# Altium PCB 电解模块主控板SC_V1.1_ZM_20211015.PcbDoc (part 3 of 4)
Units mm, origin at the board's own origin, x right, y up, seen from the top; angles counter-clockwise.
Board outline 150.25 x 100.26 mm, 2 copper layers (Top Layer, Bottom Layer); 222 components, 167 nets, 677 pads, 2045 vias.
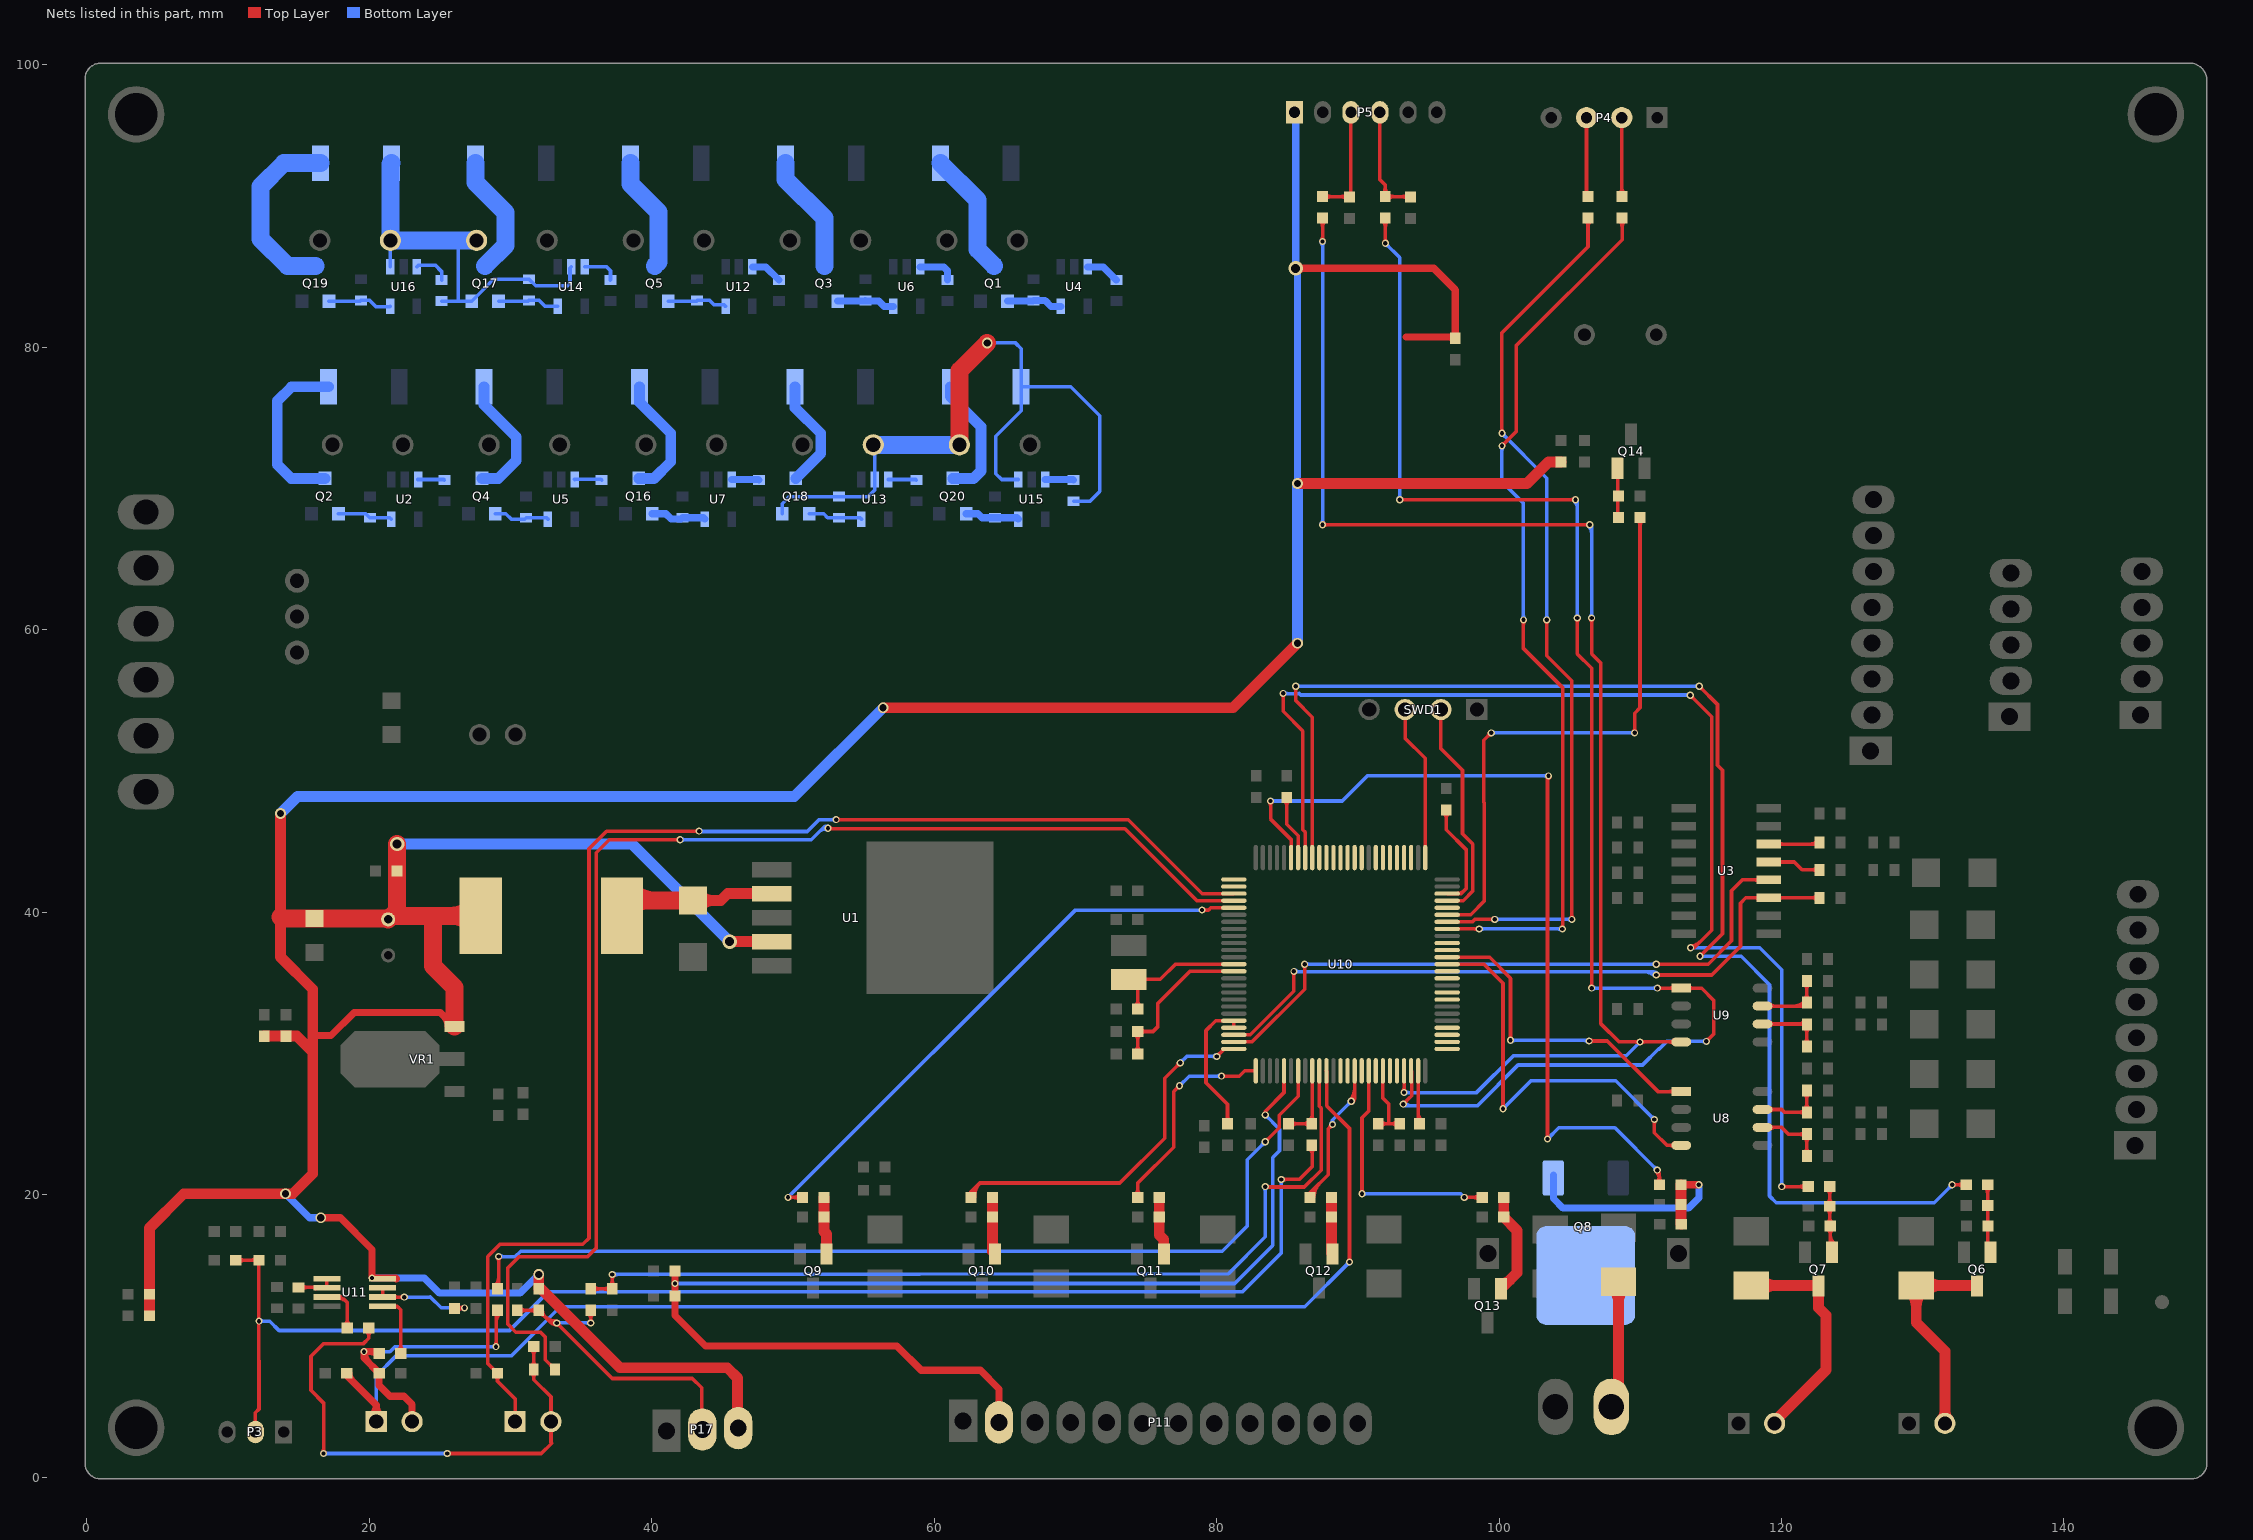
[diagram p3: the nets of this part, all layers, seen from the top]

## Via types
v1: diameter 0.762, hole 0.508, Top Layer to Bottom Layer, tented both sides, 1838 vias
v2: diameter 0.508, hole 0.305, Top Layer to Bottom Layer, tented both sides, 135 vias
v3: diameter 1.016, hole 0.635, Top Layer to Bottom Layer, tented both sides, 63 vias
v4: diameter 2.032, hole 1.524, Top Layer to Bottom Layer, tented both sides, 4 vias
v5: diameter 1.27, hole 0.762, Top Layer to Bottom Layer, tented both sides, 4 vias
v6: diameter 2.54, hole 2.032, Top Layer to Bottom Layer, tented both sides, 1 vias

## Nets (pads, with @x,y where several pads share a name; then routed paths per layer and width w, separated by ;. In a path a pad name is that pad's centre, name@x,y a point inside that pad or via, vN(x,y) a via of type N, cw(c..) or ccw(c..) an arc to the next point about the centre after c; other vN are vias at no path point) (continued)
NetC37_2: C37.2 R7.2 U10.44 | length 7.4
  Top Layer w0.254: R7.2@91.44,25.019 92.202,25.019 ; R7.2@91.62,24.839 cw(c92.053,24.406) 92.053,25.019 cw(c92.053,25.632) R7.2@91.62,25.199 ; U10.44@91.773,28.772 91.773,26.845 92.202,26.416 92.202,25.019 ; C37.2@92.784,24.839 ccw(c92.351,24.406) 92.351,25.019 ccw(c92.351,25.632) C37.2@92.784,25.199 ; C37.2@92.964,25.019 92.202,25.019
NetC38_2: C38.2 R8.2 U10.34 | length 8.3
  Top Layer w0.254: C38.2@85.09,25.019 R8.2@86.741,25.019 86.773,25.051 U10.34@86.773,28.772 ; C38.2@85.27,24.839 cw(c85.703,24.406) 85.703,25.019 cw(c85.703,25.632) C38.2@85.27,25.199 ; R8.2@86.561,24.839 ccw(c86.128,24.406) 86.128,25.019 ccw(c86.128,25.632) R8.2@86.561,25.199 ; R8.2@86.561,25.218 ccw(c86.051,25.728) 86.773,25.728 ; 86.773,25.574 ccw(c87.277,25.574) R8.2@86.921,25.218
NetC39_2: C39.2 U10.49 | length 4.8
  Top Layer w0.254: C39.2@94.181,25.218 ccw(c93.96,25.439) 94.273,25.439 ; 94.273,25.864 ccw(c95.187,25.864) C39.2@94.541,25.218 ; U10.49@94.273,28.772 94.273,25.107 C39.2@94.361,25.019
NetC40_2: C40.2 R78.1 U10.14 | length 14
  Top Layer w0.254: R78.1@74.242,30.152 ccw(c73.809,30.585) 74.422,30.585 ccw(c75.035,30.585) R78.1@74.602,30.152 ; C40.2@74.242,31.38 cw(c73.809,30.946) 74.422,30.946 cw(c75.035,30.946) C40.2@74.602,31.38 ; R78.1@74.422,29.972 C40.2@74.422,31.559 75.501,31.559 75.819,31.877 75.819,33.528 78.113,35.822 U10.14@81.223,35.822 ; C40.2@74.621,31.38 cw(c75.054,30.946) 75.054,31.559 cw(c75.054,32.173) C40.2@74.621,31.739
NetC41_2: C41.2 C43.1 Q17.2 R101.2 R103.1 R112.1 U14.2 U16.1 | length 29
  Bottom Layer w0.254: U16.1@21.478,85.7 21.478,87.558 C43.1@21.499,87.579 ; R112.1@25.121,83.272 26.314,83.272 ; 26.365,87.579 26.314,87.528 26.314,83.272 ; U14.2@34.303,85.7 34.214,85.611 34.214,84.506 34.061,84.353 31.781,84.353 R101.2@31.312,84.822 28.803,84.822 Q17.2@27.255,83.275 27.252,83.272 26.314,83.272
  Bottom Layer w1.27: R103.1@21.561,93.04 21.499,92.979 C43.1@21.499,87.579 26.365,87.579 C41.2@27.599,87.579
NetC42_2: C42.2 C44.1 Q18.2 R102.2 R107.1 R111.1 U13.2 U15.1 | length 52.9
  Top Layer w1.27: C44.1@61.787,73.101 61.787,78.348 v1(63.754,80.315)
  Bottom Layer w0.254: Q18.2@49.253,68.219 49.253,68.938 49.752,69.437 R102.2@53.245,69.437 55.34,69.437 55.804,69.901 U13.2@55.804,70.644 55.804,72.985 C42.2@55.688,73.101 ; v1(63.754,80.315) 65.761,80.315 66.163,79.912 R107.1@66.163,77.216 ; U15.1@65.954,70.644 64.78,70.644 64.364,71.061 64.364,73.711 66.163,75.51 R107.1@66.163,77.216 ; R111.1@69.875,69.105 71.035,69.105 71.73,69.799 71.73,75.159 69.672,77.216 R107.1@66.163,77.216
  Bottom Layer w1.27: C42.2@55.688,73.101 C44.1@61.787,73.101
NetC45_2: C45.2 U10.73 | length 9.1
  Top Layer w0.254: C45.2@96.086,47.045 cw(c95.653,46.612) 96.266,46.612 cw(c96.879,46.612) C45.2@96.446,47.045 ; C45.2@96.266,47.244 96.266,45.847 97.663,44.45 97.663,41.656 97.329,41.322 U10.73@96.323,41.322 ; U10.73@97.073,41.345 ccw(c97.073,42.019) 97.549,41.542
NetC46_2: C46.2 P11.2 R48.1 U10.30 | length 88.5
  Top Layer w0.254: v2(83.439,25.654) 83.439,25.899 84.773,27.233 U10.30@84.773,28.772
  Top Layer w0.508: R48.1@41.656,14.605 v2(41.656,13.716) C46.2@41.656,12.827 41.656,11.455 43.815,9.296 57.353,9.296 59.08,7.569 63.271,7.569 64.592,6.248 P11.2@64.592,3.888
  Bottom Layer w0.254: v2(41.656,13.716) 81.28,13.716 83.972,16.408 83.972,22.631 84.455,23.114 84.455,24.638 v2(83.439,25.654) ; v2@41.746,13.626 cw(c41.963,13.409) 41.963,13.716 cw(c41.963,14.023) v2@41.746,13.806 ; v2@83.439,25.527 cw(c83.439,25.22) 83.656,25.437 cw(c83.873,25.654) v2@83.566,25.654
NetC50_1: C50.1 U10.13 Y1.1 | length 11.2
  Top Layer w0.254: C50.1@74.242,33.327 ccw(c73.809,33.76) 74.422,33.76 ccw(c75.035,33.76) C50.1@74.602,33.327 ; C50.1@74.422,33.147 74.422,34.614 Y1.1@73.787,35.249 76.016,35.249 77.089,36.322 U10.13@81.223,36.322
NetD3_2: D3.2 L1.1 U1.2 | length 16.9
  Top Layer w0.762: L1.1@37.893,39.751 L1.1@38.972,40.83 ; D3.2@42.926,40.83 44.894,40.83 45.388,41.324 U1.2@48.514,41.324 ; D3.2@43.364,40.392 cw(c44.42,39.336) 44.42,40.83 cw(c44.42,42.324) D3.2@43.364,41.268
  Top Layer w1.27: L1.1@38.505,40.339 cw(c39.689,39.155) 39.689,40.83 ; L1.1@38.505,41.563 ccw(c40.273,43.331) 40.273,40.83 ; L1.1@38.972,40.83 D3.2@42.926,40.83
NetD6_1: D6.1 P8.2 Q6.3 | length 21
  Top Layer w0.762: D6.1@129.102,13.141 cw(c128.046,12.085) 129.54,12.085 cw(c131.034,12.085) D6.1@129.978,13.141 ; D6.1@130.228,13.141 cw(c131.284,12.085) 131.284,13.579 cw(c131.284,15.073) D6.1@130.228,14.017 ; P8.2@131.311,4.071 ccw(c130.681,4.701) 131.572,4.701 ccw(c132.463,4.701) P8.2@131.833,4.071 ; P8.2@131.572,3.81 131.572,8.915 129.54,10.947 D6.1@129.54,13.579 133.811,13.579 Q6.3@133.858,13.532
NetD7_1: D7.1 P9.2 Q7.3 | length 18.6
  Top Layer w0.762: D7.1@117.856,13.579 122.571,13.579 Q7.3@122.618,13.532 122.618,12.002 123.158,11.462 123.158,7.588 119.507,3.937 P9.2@119.507,3.81 ; D7.1@118.544,13.141 cw(c119.6,12.085) 119.6,13.579 cw(c119.6,15.073) D7.1@118.544,14.017
NetD8_1: D8.1 P10.2 Q8.3 | length 13
  Top Layer w0.762: P10.2@107.315,3.937 107.315,5.182 108.458,6.325 D8.1@108.458,13.833 D8.1@108.632,13.659 ; D8.1@108.02,13.395 cw(c106.964,12.339) 108.458,12.339 cw(c109.952,12.339) D8.1@108.896,13.395
NetL3_2: L3.2 U10.21 U10.22 | length 11
  Top Layer w0.254: L3.2@80.592,25.218 ccw(c80.159,25.651) 80.772,25.651 ccw(c81.385,25.651) L3.2@80.952,25.218 ; L3.2@80.772,25.019 80.772,26.416 79.248,27.94 79.248,31.623 79.947,32.322 U10.21@81.223,32.322 U10.22@81.223,31.822
NetP1_1: P1.1 TVS5.2 U10.36 | length 97.4
  Top Layer w0.254: U10.36@87.773,28.772 87.808,28.737 87.808,26.289 89.408,24.689 v2(89.408,15.24) ; v2@89.318,15.33 ccw(c89.101,15.547) 89.408,15.547 ccw(c89.715,15.547) v2@89.498,15.33
  Top Layer w0.508: TVS5.2@18.415,7.366 18.415,7.188 20.498,5.105 ; TVS5.2@18.561,7.366 ccw(c19.343,7.366) 18.79,6.813 ; P1.1@20.153,4.294 ccw(c19.37,5.105) 20.498,5.105 ; P1.1@20.498,3.937 20.498,5.105 ; P1.1@20.842,4.294 cw(c21.626,5.105) 20.498,5.105
  Bottom Layer w0.254: P1.1@20.498,3.937 20.498,7.188 21.895,8.585 30.048,8.585 33.528,12.065 86.233,12.065 v2(89.408,15.24) ; v2@89.281,15.24 cw(c88.974,15.24) 89.191,15.023 cw(c89.408,14.806) v2@89.408,15.113
NetP1_2: P1.2 R14.2 R16.1 TVS6.2 | length 24
  Top Layer w0.254: v2@28.892,9.335 ccw(c28.675,9.552) 28.981,9.552 ccw(c29.288,9.552) v2@29.071,9.335 ; R14.2@28.903,11.612 cw(c28.715,11.424) R14.2@28.981,11.424 ; v2(28.981,9.246) 28.981,11.709 R14.2@29.083,11.811 ; 28.981,10.934 cw(c29.941,10.934) R14.2@29.263,11.612
  Top Layer w0.508: 19.957,8.11 cw(c20.738,8.89) v2(19.634,8.89) ; 20.069,8.89 cw(c20.069,8.15) R16.1@20.592,8.673 ; R16.1@20.701,8.763 20.574,8.89 v2(19.634,8.89) ; P1.2@23.038,3.937 23.038,5.156 22.466,5.728 21.467,5.728 20.701,6.494 TVS6.2@20.701,7.366 19.634,8.433 v2(19.634,8.89)
  Bottom Layer w0.254: v2(19.634,8.89) 21.463,8.89 21.819,9.246 v2(28.981,9.246) ; v2@19.724,8.8 cw(c19.941,8.583) 19.941,8.89 cw(c19.941,9.197) v2@19.724,8.98 ; v2@28.892,9.156 ccw(c28.675,8.939) 28.675,9.246 ccw(c28.675,9.552) v2@28.892,9.335
NetP2_1: P2.1 TVS7.2 U10.3 | length 99.1
  Top Layer w0.254: TVS7.2@28.91,7.18 cw(c28.538,6.782) 29.083,6.782 ; TVS7.2@29.256,7.18 ccw(c29.628,6.782) 29.083,6.782 ; P2.1@30.328,3.937 30.328,5.537 29.083,6.782 ; v2@43.268,45.656 ccw(c43.051,45.439) 43.051,45.745 ccw(c43.051,46.052) v2@43.268,45.835 ; v2(43.358,45.745) 36.805,45.745 35.56,44.501 35.56,16.916 35.128,16.485 29.261,16.485 28.397,15.621 28.397,8.052 TVS7.2@29.083,7.366 29.083,6.782 ; v2(53.061,46.558) 73.736,46.558 78.972,41.322 U10.3@81.223,41.322 ; v2@53.15,46.468 cw(c53.367,46.252) 53.367,46.558 cw(c53.367,46.865) v2@53.15,46.648
  Bottom Layer w0.254: v2(43.358,45.745) 43.383,45.72 51.003,45.72 51.841,46.558 v2(53.061,46.558) ; v2@43.448,45.835 ccw(c43.726,46.113) 43.726,45.72 ; v2@52.971,46.468 ccw(c52.754,46.252) 52.754,46.558 ccw(c52.754,46.865) v2@52.971,46.648
NetP2_2: P2.2 R23.2 R25.1 TVS12.2 | length 42
  Top Layer w0.254: v2@16.674,1.766 ccw(c16.457,1.983) 16.764,1.983 ccw(c17.071,1.983) v2@16.854,1.766 ; v2(16.764,1.676) 16.764,5.258 15.875,6.147 15.875,8.56 16.777,9.461 19.596,9.461 19.964,9.83 R25.1@19.964,10.566 ; R25.1@19.785,10.387 cw(c19.351,9.953) 19.964,9.953 cw(c20.578,9.953) R25.1@20.144,10.387 ; v2(25.527,1.676) 32.182,1.676 32.918,2.413 32.868,2.464 P2.2@32.868,3.937 32.868,5.688 31.647,6.909 R23.2@31.647,7.62 ; v2@25.617,1.587 cw(c25.834,1.37) 25.834,1.676 cw(c25.834,1.983) v2@25.617,1.766 ; TVS12.2@31.469,9.066 cw(c31.035,8.632) 31.648,8.632 cw(c32.262,8.632) TVS12.2@31.828,9.066 ; R23.2@31.489,7.387 cw(c31.109,7.007) 31.647,7.007 cw(c32.185,7.007) R23.2@31.805,7.387 ; R23.2@31.489,7.853 ccw(c31.105,8.237) 31.648,8.237 ; R23.2@31.648,7.62 TVS12.2@31.648,9.246 ; 31.648,8.23 ccw(c32.182,8.23) R23.2@31.805,7.853
  Bottom Layer w0.254: v2(16.764,1.676) v2(25.527,1.676) ; v2@16.854,1.587 cw(c17.071,1.37) 17.071,1.676 cw(c17.071,1.983) v2@16.854,1.766 ; v2@25.437,1.587 ccw(c25.22,1.37) 25.22,1.676 ccw(c25.22,1.983) v2@25.437,1.766
NetP3_2: P3.2 R6.2 R8.1 TVS2.2 | length 102
  Top Layer w0.254: TVS2.2@10.541,15.367 R6.2@12.192,15.367 12.167,15.342 12.167,8.284 12.192,8.259 12.192,4.826 11.938,4.572 P3.2@11.938,3.2 ; TVS2.2@10.74,15.187 cw(c11.173,14.754) 11.173,15.367 cw(c11.173,15.98) TVS2.2@10.74,15.547 ; 11.56,15.367 ccw(c11.56,15.98) R6.2@11.993,15.547 ; v2(84.582,21.082) 85.852,21.082 86.766,21.996 86.766,23.47 R8.1@86.741,23.495 ; v2@84.672,20.992 cw(c84.889,20.775) 84.889,21.082 cw(c84.889,21.389) v2@84.672,21.172 ; R8.1@86.561,23.296 cw(c86.066,22.801) 86.766,22.801 ; 86.766,22.924 cw(c87.293,22.924) R8.1@86.921,23.296
  Bottom Layer w0.254: v2(12.192,11.049) 12.954,11.049 13.614,10.389 29.934,10.389 32.69,13.144 81.852,13.144 84.582,15.875 v2(84.582,21.082) ; v2@12.282,10.959 cw(c12.499,10.742) 12.499,11.049 cw(c12.499,11.356) v2@12.282,11.139 ; v2@84.492,20.992 cw(c84.275,20.775) 84.582,20.775 cw(c84.889,20.775) v2@84.672,20.992
NetP4_2: P4.2 R11.1 | length 6.6
  Top Layer w0.254: R11.1@108.532,90.877 ccw(c108.147,91.262) 108.692,91.262 ; 108.692,91.358 ccw(c109.373,91.358) R11.1@108.892,90.877 ; P4.2@108.692,96.266 108.692,90.698 R11.1@108.712,90.678
NetP4_3: P4.3 R9.1 | length 5.6
  Top Layer w0.254: P4.3@106.192,96.266 106.192,90.785 R9.1@106.299,90.678
NetP5_3: P5.3 R10.1 TVS3.2 | length 9.9
  Top Layer w0.254: R10.1@87.503,90.678 89.383,90.678 TVS3.2@89.408,90.653 89.511,90.755 P5.3@89.511,96.641 ; R10.1@87.683,90.498 cw(c88.116,90.065) 88.116,90.678 cw(c88.116,91.291) R10.1@87.683,90.858 ; 88.779,90.678 cw(c88.779,90.043) TVS3.2@89.228,90.492 ; 88.81,90.678 ccw(c88.81,91.269) TVS3.2@89.228,90.851
NetP5_4: P5.4 R12.1 TVS4.2 | length 10.8
  Top Layer w0.254: P5.4@91.561,96.641 91.561,91.884 91.928,91.516 91.928,90.698 R12.1@91.948,90.678 93.701,90.678 TVS4.2@93.726,90.653 ; R12.1@91.768,90.877 ccw(c91.383,91.262) 91.928,91.262 ; 91.928,91.358 ccw(c92.609,91.358) R12.1@92.128,90.877 ; R12.1@92.128,90.498 cw(c92.561,90.065) 92.561,90.678 cw(c92.561,91.291) R12.1@92.128,90.858 ; 93.097,90.678 cw(c93.097,90.043) TVS4.2@93.546,90.492 ; 93.128,90.678 ccw(c93.128,91.269) TVS4.2@93.546,90.851
NetP17_2: P17.2 R19.1 R50.2 TVS11.2 | length 28.6
  Top Layer w0.254: TVS11.2@30.48,11.811 R50.2@32.004,11.811 32.893,10.922 v2(33.274,10.922) 37.211,6.985 42.875,6.985 43.536,6.325 P17.2@43.536,4.091 ; TVS11.2@30.66,11.631 cw(c31.093,11.198) 31.093,11.811 cw(c31.093,12.424) TVS11.2@30.66,11.991 ; R50.2@31.824,11.631 ccw(c31.391,11.198) 31.391,11.811 ccw(c31.391,12.424) R50.2@31.824,11.991 ; R50.2@32.004,11.538 cw(c32.004,10.879) 32.47,11.345 ; R50.2@32.258,11.792 ccw(c32.825,11.792) 32.424,11.391 ; 32.407,11.408 ccw(c33.274,12.275) v2@33.274,11.049 ; 32.84,10.975 ccw(c33.274,11.408) 33.274,10.795 cw(c33.274,10.488) 33.491,10.705 cw(c33.708,10.922) v2@33.401,10.922 ; v2@33.184,10.832 ccw(c32.967,10.615) 32.967,10.922 ccw(c32.967,11.229) v2@33.184,11.012 ; R19.1@35.507,11.612 cw(c35.074,11.179) 35.687,11.179 cw(c36.3,11.179) R19.1@35.867,11.612 ; v2@35.597,11.012 ccw(c35.38,11.229) 35.687,11.229 ccw(c35.994,11.229) v2@35.777,11.012 ; v2(35.687,10.922) R19.1@35.687,11.811
  Bottom Layer w0.254: v2(33.274,10.922) v2(35.687,10.922) ; v2@33.364,10.832 cw(c33.581,10.615) 33.581,10.922 cw(c33.581,11.229) v2@33.364,11.012 ; v2@35.597,10.832 ccw(c35.38,10.615) 35.38,10.922 ccw(c35.38,11.229) v2@35.597,11.012
NetQ1_1: Q1.1 R28.1 U4.5 | length 4
  Bottom Layer w0.508: Q1.1@65.187,83.275 66.983,83.275 R28.1@67.031,83.322 67.858,83.322 68.281,82.9 U4.5@68.976,82.9
NetQ1_3: Q1.3 R1.2 | length 8.8
  Bottom Layer w1.27: R1.2@60.456,93.04 63.068,90.428 63.068,86.943 Q1.3@64.237,85.775
NetQ2_1: Q2.1 R29.1 U2.5 | length 3.9
  Bottom Layer w0.254: Q2.1@17.816,68.219 19.758,68.219 R29.1@20.041,67.937 21.462,67.937 U2.5@21.554,67.844
NetQ2_3: Q2.3 R13.2 | length 12.3
  Bottom Layer w0.762: Q2.3@16.866,70.719 14.473,70.719 13.487,71.704 13.487,76.2 14.503,77.216 R13.2@17.123,77.216
NetQ3_1: Q3.1 R66.1 U6.5 | length 4.1
  Bottom Layer w0.508: Q3.1@53.176,83.275 55.076,83.275 R66.1@55.124,83.322 55.16,83.287 56.083,83.287 56.47,82.9 U6.5@57.102,82.9
NetQ3_3: Q3.3 R30.2 | length 8.4
  Bottom Layer w1.27: R30.2@49.482,93.04 49.482,91.894 52.226,89.15 Q3.3@52.226,85.775
NetQ4_1: Q4.1 R67.1 U5.5 | length 4
  Bottom Layer w0.254: Q4.1@28.928,68.219 29.673,68.219 30.048,67.843 31.015,67.843 R67.1@31.109,67.937 32.562,67.937 U5.5@32.654,67.844
NetQ4_3: Q4.3 R53.2 | length 9.1
  Bottom Layer w0.762: Q4.3@27.978,70.719 29.139,70.719 30.404,71.984 30.404,73.66 28.133,75.93 R53.2@28.133,77.216
NetQ5_1: Q5.1 R89.1 U12.5 | length 4.3
  Bottom Layer w0.254: Q5.1@41.166,83.275 43.17,83.275 R89.1@43.218,83.322 44.109,83.322 44.399,83.033 45.094,83.033 U12.5@45.227,82.9
NetQ5_3: Q5.3 R68.2 | length 8.2
  Bottom Layer w1.27: R68.2@38.508,93.04 38.508,91.565 40.488,89.586 40.488,86.046 Q5.3@40.216,85.775
NetQ6_1: Q6.1 R31.1 R34.1 TVS8.2 | length 5.8
  Top Layer w0.254: R31.1@134.415,20.521 cw(c133.981,20.088) 134.595,20.088 cw(c135.208,20.088) R31.1@134.774,20.521 ; R31.1@134.595,20.701 R34.1@134.595,19.241 134.595,16.145 Q6.1@134.808,15.932
NetQ7_1: Q7.1 R32.1 R35.1 TVS9.2 | length 11.1
  Top Layer w0.254: R35.1@123.239,18.997 cw(c122.805,18.564) 123.419,18.564 cw(c124.032,18.564) R35.1@123.598,18.997 ; R35.1@123.239,19.357 ccw(c122.805,19.79) 123.419,19.79 ccw(c124.032,19.79) R35.1@123.598,19.357 ; R32.1@123.239,20.394 cw(c122.805,19.961) 123.419,19.961 cw(c124.032,19.961) R32.1@123.598,20.394 ; TVS9.2@123.245,17.96 ccw(c122.827,18.378) 123.419,18.378 ; TVS9.2@123.264,17.6 cw(c122.831,17.167) 123.444,17.167 cw(c124.057,17.167) TVS9.2@123.624,17.6 ; Q7.1@123.358,16.468 ccw(c123.15,16.676) Q7.1@123.444,16.676 ; 123.419,18.409 ccw(c124.054,18.409) TVS9.2@123.605,17.96 ; R32.1@123.419,20.574 R35.1@123.419,19.177 123.419,17.805 TVS9.2@123.444,17.78 123.444,16.056 Q7.1@123.568,15.932 ; Q7.1@123.444,16.664 ccw(c123.975,16.664) Q7.1@123.6,16.288 ; 123.444,17.277 ccw(c124.588,17.277) Q7.1@123.779,16.468
NetQ8_1: Q8.1 R33.1 R36.1 TVS10.2 | length 17.6
  Top Layer w0.508: R33.1@112.878,20.701 v2(114.148,20.701)
  Top Layer w0.762: R33.1@112.878,20.701 R36.1@112.878,19.304 112.878,17.932 TVS10.2@112.903,17.907
  Bottom Layer w0.508: Q8.1@103.847,21.403 103.847,19.724 104.521,19.05 113.411,19.05 114.148,19.787 v2(114.148,20.701)
NetQ9_1: Q9.1 R37.1 R42.1 | length 4.1
  Top Layer w0.762: R37.1@52.197,19.812 R42.1@52.197,18.415 52.197,17.399 52.385,17.211 Q9.1@52.385,15.805
NetQ10_1: Q10.1 R38.1 R43.1 | length 4.7
  Top Layer w0.762: 64.135,16.69 ccw(c64.883,16.69) Q10.1@64.354,16.161 ; R38.1@64.135,19.812 R43.1@64.135,18.415 64.135,15.993 Q10.1@64.323,15.805
NetQ11_1: Q11.1 R39.1 R44.1 | length 4.1
  Top Layer w0.762: R39.1@75.946,19.812 R44.1@75.946,18.415 75.946,17.145 76.261,16.83 Q11.1@76.261,15.805
NetQ12_1: Q12.1 R40.1 R45.1 | length 4
  Top Layer w0.762: R40.1@88.138,19.812 R45.1@88.138,18.415 88.138,15.866 Q12.1@88.199,15.805
NetQ13_1: Q13.1 R41.1 R46.1 | length 8
  Top Layer w0.762: Q13.1@100.137,13.341 101.27,14.474 101.27,17.475 R46.1@100.33,18.415 R41.1@100.33,19.812 ; Q13.1@100.137,13.71 ccw(c100.137,14.601) 100.767,13.971
NetQ14_1: Q14.1 R57.2 R59.1 | length 3.5
  Top Layer w0.254: Q14.1@108.397,71.444 108.397,68.006 R57.2@108.458,67.945
NetQ16_1: Q16.1 R90.1 U7.5 | length 3.9
  Bottom Layer w0.508: Q16.1@40.041,68.219 41.001,68.219 41.377,67.843 42.083,67.843 R90.1@42.177,67.937 43.661,67.937 U7.5@43.754,67.844
NetQ16_3: Q16.3 R83.2 | length 9
  Bottom Layer w0.762: Q16.3@39.091,70.719 40.163,70.719 41.351,71.907 41.351,73.914 39.143,76.122 R83.2@39.143,77.216
NetQ17_1: Q17.1 R101.1 U14.5 | length 4.4
  Bottom Layer w0.254: Q17.1@29.155,83.275 31.264,83.275 R101.1@31.312,83.322 32.029,83.322 32.452,82.9 U14.5@33.353,82.9
NetQ17_3: Q17.3 R91.2 | length 8.7
  Bottom Layer w1.27: R91.2@27.535,93.04 27.535,91.668 29.642,89.56 29.642,87.211 Q17.3@28.205,85.775
NetQ18_1: Q18.1 R102.1 U13.5 | length 3.9
  Bottom Layer w0.254: Q18.1@51.153,68.219 52.177,68.219 52.451,67.945 53.236,67.945 R102.1@53.245,67.937 54.761,67.937 U13.5@54.854,67.844
NetQ18_3: Q18.3 R95.2 | length 8
  Bottom Layer w0.762: R95.2@50.153,77.216 50.153,75.729 51.971,73.911 51.971,72.487 Q18.3@50.203,70.719
NetQ19_1: Q19.1 R113.1 U16.5 | length 4.5
  Bottom Layer w0.254: Q19.1@17.145,83.275 19.358,83.275 R113.1@19.406,83.322 20.03,83.322 20.472,82.88 21.459,82.88 U16.5@21.478,82.9
NetQ19_3: Q19.3 R103.2 | length 13.4
  Bottom Layer w1.27: Q19.3@16.195,85.775 14.2,85.775 12.294,87.681 12.294,91.389 13.945,93.04 R103.2@16.561,93.04
NetQ20_1: Q20.1 R114.1 U15.5 | length 3.8
  Bottom Layer w0.508: Q20.1@62.266,68.219 63.099,68.219 63.381,67.937 R114.1@64.313,67.937 65.861,67.937 U15.5@65.954,67.844
NetQ20_3: Q20.3 R107.2 | length 9.1
  Bottom Layer w0.762: R107.2@61.163,77.216 61.163,76.53 63.322,74.371 63.322,71.247 62.794,70.719 Q20.3@61.316,70.719
NetR9_2: R9.2 U10.69 | length 68
  Top Layer w0.254: U10.69@96.323,39.322 98.123,39.322 98.298,39.497 v2(99.695,39.497) ; v2@99.605,39.407 ccw(c99.388,39.19) 99.388,39.497 ccw(c99.388,39.804) v2@99.605,39.587 ; v2@100.113,74.004 ccw(c99.896,74.221) 100.203,74.221 ccw(c100.51,74.221) v2@100.293,74.004 ; v2(100.203,73.914) 100.203,81.026 106.299,87.122 R9.2@106.299,89.154 ; v2@103.288,60.616 cw(c103.071,60.399) 103.378,60.399 cw(c103.685,60.399) v2@103.468,60.616 ; v2(103.378,60.706) 103.378,58.166 105.156,56.388 v2(105.156,39.497) ; v2@105.066,39.587 ccw(c104.849,39.804) 105.156,39.804 ccw(c105.463,39.804) v2@105.246,39.587 ; R9.2@106.119,88.955 cw(c105.686,88.522) 106.299,88.522 cw(c106.912,88.522) R9.2@106.479,88.955
  Bottom Layer w0.254: v2(99.695,39.497) v2(105.156,39.497) ; v2@99.785,39.407 cw(c100.002,39.19) 100.002,39.497 cw(c100.002,39.804) v2@99.785,39.587 ; v2@100.203,73.787 cw(c100.203,73.48) 100.42,73.697 cw(c100.637,73.914) v2@100.33,73.914 ; v2(100.203,73.914) 103.378,70.739 v2(103.378,60.706) ; v2@103.288,60.796 ccw(c103.071,61.013) 103.378,61.013 ccw(c103.685,61.013) v2@103.468,60.796 ; v2@105.066,39.407 ccw(c104.849,39.19) 104.849,39.497 ccw(c104.849,39.804) v2@105.066,39.587
NetR11_2: R11.2 U10.68 | length 68.5
  Top Layer w0.254: U10.68@96.323,38.822 v2(98.592,38.822) ; v2@98.502,38.732 ccw(c98.285,38.515) 98.285,38.822 ccw(c98.285,39.129) v2@98.502,38.912 ; v2(100.203,73.025) 101.219,74.041 101.219,80.137 108.712,87.63 R11.2@108.712,89.154 ; v2@100.203,73.152 ccw(c100.203,73.459) 100.42,73.242 ccw(c100.637,73.025) v2@100.33,73.025 ; v2@101.637,60.616 cw(c101.42,60.399) 101.727,60.399 cw(c102.034,60.399) v2@101.817,60.616 ; v2(101.727,60.706) 101.727,58.674 104.521,55.88 104.521,38.862 v2(104.481,38.822) ; v2@104.391,38.912 ccw(c104.078,39.225) 104.521,39.225 ; R11.2@108.532,88.955 cw(c108.099,88.522) 108.712,88.522 cw(c109.325,88.522) R11.2@108.892,88.955
  Bottom Layer w0.254: v2(98.592,38.822) v2(104.481,38.822) ; v2@98.682,38.732 cw(c98.899,38.515) 98.899,38.822 cw(c98.899,39.129) v2@98.682,38.912 ; v2@100.113,72.935 cw(c99.896,72.718) 100.203,72.718 cw(c100.51,72.718) v2@100.293,72.935 ; v2(100.203,73.025) 100.203,70.485 101.727,68.961 v2(101.727,60.706) ; v2@101.637,60.796 ccw(c101.42,61.013) 101.727,61.013 ccw(c102.034,61.013) v2@101.817,60.796 ; v2@104.391,38.732 ccw(c104.174,38.515) 104.174,38.822 ccw(c104.174,39.129) v2@104.391,38.912
NetR14_1: R14.1 U10.32 | length 71.6
  Top Layer w0.254: R14.1@28.903,13.534 ccw(c28.286,14.151) 29.159,14.151 ; v2@29.069,15.531 cw(c28.853,15.314) 29.159,15.314 cw(c29.466,15.314) v2@29.249,15.531 ; R14.1@29.083,13.335 29.159,13.411 v2(29.159,15.621) ; 29.159,13.783 ccw(c29.512,13.783) R14.1@29.263,13.534 ; v2(83.439,23.749) 84.43,24.74 84.43,25.629 85.773,26.972 U10.32@85.773,28.772 ; v2@83.439,23.876 ccw(c83.439,24.183) 83.656,23.966 ccw(c83.873,23.749) v2@83.566,23.749
  Bottom Layer w0.254: v2(29.159,15.621) 30.353,15.621 30.734,16.002 80.391,16.002 82.169,17.78 82.169,22.479 v2(83.439,23.749) ; v2@29.249,15.531 cw(c29.466,15.314) 29.466,15.621 cw(c29.466,15.928) v2@29.249,15.711 ; v2@83.312,23.749 cw(c83.005,23.749) 83.222,23.532 cw(c83.439,23.315) v2@83.439,23.622
NetR16_2: R16.2 U11.5 | length 5.9
  Top Layer w0.254: U11.5@20.949,12.106 21.981,12.106 22.225,11.862 R16.2@22.225,8.763 ; U11.5@21.728,12.039 cw(c21.871,11.714) 22.122,11.965 ; R16.2@22.045,8.943 ccw(c21.612,9.376) 22.225,9.376 ccw(c22.838,9.376) R16.2@22.405,8.943
NetR18_2: R18.2 U11.6 U11.7 | length 9.4
  Top Layer w0.254: U11.6@20.949,12.756 U11.7@20.949,13.406 ; 21.914,12.756 21.919,12.751 v2(22.479,12.751) ; v2@22.389,12.661 ccw(c22.172,12.444) 22.172,12.751 ccw(c22.172,13.057) v2@22.389,12.841 ; R18.2@26.035,11.938 26.086,11.989 v2(26.746,11.989) ; R18.2@26.215,11.777 cw(c26.725,11.267) v2@26.725,11.989 ; R18.2@26.215,12.137 ccw(c26.571,12.493) v2@26.571,11.989 ; v2@26.656,11.899 ccw(c26.44,11.682) 26.44,11.989 ccw(c26.44,12.295) v2@26.656,12.079
  Bottom Layer w0.254: v2(22.479,12.751) 24.323,12.751 24.328,12.756 25.095,11.989 v2(26.746,11.989) ; v2@22.569,12.661 cw(c22.786,12.444) 22.786,12.751 cw(c22.786,13.057) v2@22.569,12.841 ; v2@26.656,11.899 ccw(c26.44,11.682) 26.44,11.989 ccw(c26.44,12.295) v2@26.656,12.079
NetR19_2: R19.2 R22.2 U10.35 | length 69.5
  Top Layer w0.254: R19.2@35.687,13.335 R22.2@37.211,13.335 v2(37.211,14.351) ; R19.2@35.867,13.155 cw(c36.3,12.722) 36.3,13.335 cw(c36.3,13.948) R19.2@35.867,13.515 ; R22.2@37.031,13.155 ccw(c36.598,12.722) 36.598,13.335 ccw(c36.598,13.948) R22.2@37.031,13.515 ; R22.2@37.031,13.534 ccw(c36.598,13.967) 37.211,13.967 ccw(c37.824,13.967) R22.2@37.391,13.534 ; v2@37.121,14.261 cw(c36.904,14.044) 37.211,14.044 cw(c37.518,14.044) v2@37.301,14.261 ; v2(83.439,20.574) 83.464,20.549 86.208,20.549 87.401,21.742 87.401,26.137 87.273,26.265 U10.35@87.273,28.772 ; v2@83.529,20.664 ccw(c83.807,20.942) 83.807,20.549
  Bottom Layer w0.254: v2(37.211,14.351) 80.835,14.414 83.439,17.018 v2@83.439,20.447 ; v2@37.301,14.261 cw(c37.518,14.045) 37.518,14.351 cw(c37.517,14.658) v2@37.301,14.441 ; v2@83.349,20.484 cw(c83.132,20.267) 83.439,20.267 cw(c83.746,20.267) v2@83.529,20.484
NetR23_1: R23.1 U10.4 | length 95.1
  Top Layer w0.254: R23.1@33.147,7.62 32.461,8.306 32.461,9.931 32.131,10.262 30.378,10.262 29.82,10.82 29.82,14.834 30.582,15.596 35.433,15.596 36.068,16.231 36.068,44.221 36.982,45.136 v2(42.012,45.136) ; v2@41.922,45.046 ccw(c41.705,44.829) 41.705,45.136 ccw(c41.705,45.442) v2@41.922,45.226 ; v2(52.476,45.949) 52.502,45.923 73.508,45.923 78.609,40.822 U10.4@81.223,40.822 ; v2@52.566,46.038 ccw(c52.844,46.317) 52.844,45.923
  Bottom Layer w0.254: v2(42.012,45.136) 51.308,45.136 52.121,45.949 v2(52.476,45.949) ; v2@42.101,45.046 cw(c42.318,44.829) 42.318,45.136 cw(c42.318,45.442) v2@42.101,45.226 ; 51.943,45.771 cw(c52.223,45.491) v2@52.415,45.837 ; 52.182,46.009 cw(c52.393,45.798) v2@52.538,46.06 ; v2@52.387,45.859 ccw(c52.17,45.642) 52.17,45.949 ccw(c52.17,46.255) v2@52.387,46.038
NetR24_2: R24.2 U11.1 U11.2 | length 3.7
  Top Layer w0.254: R24.2@14.986,13.438 U11.2@16.999,13.438 ; R24.2@15.219,13.28 cw(c15.599,12.9) 15.599,13.438 cw(c15.599,13.976) R24.2@15.219,13.596 ; 15.995,13.438 cw(c15.995,13.153) U11.2@16.197,13.354 ; U11.2@16.999,13.406 U11.2@16.999,13.438 ; U11.1@16.999,14.056 U11.2@16.999,13.438
NetR25_2: R25.2 U11.3 | length 5.6
  Top Layer w0.254: U11.3@16.999,12.756 18.054,12.756 18.44,12.37 R25.2@18.44,10.566 ; U11.3@17.749,12.683 cw(c17.749,11.769) 18.395,12.415 ; U11.3@17.777,12.689 cw(c17.928,12.325) 18.207,12.603 ; R25.2@18.261,10.746 ccw(c17.827,11.18) 18.44,11.18 ccw(c19.054,11.18) R25.2@18.62,10.746
NetR26_2: R26.2 U2.3 | length 1.9
  Bottom Layer w0.254: U2.3@23.454,70.644 25.285,70.644 R26.2@25.324,70.605
NetR27_2: R27.2 U4.3 | length 2.4
  Bottom Layer w0.508: U4.3@70.876,85.7 71.97,85.7 R27.2@72.898,84.772
NetR31_2: R31.2 U10.92 | length 101.9
  Top Layer w0.254: v2@85.508,55.917 cw(c85.291,55.7) 85.598,55.7 cw(c85.905,55.7) v2@85.688,55.917 ; v2(85.598,56.007) 85.598,54.991 86.773,53.816 U10.92@86.773,43.872 ; v2@114.173,55.88 cw(c114.173,55.573) 114.39,55.79 cw(c114.607,56.007) v2@114.3,56.007 ; v2(114.173,56.007) 115.468,54.712 115.468,50.419 115.824,50.063 115.824,38.481 v2(114.224,36.881) ; v2@114.224,37.008 ccw(c114.224,37.314) 114.441,37.098 ccw(c114.657,36.881) v2@114.351,36.881 ; v2(132.08,20.701) R31.2@133.071,20.701 ; v2@132.17,20.611 cw(c132.387,20.394) 132.387,20.701 cw(c132.387,21.008) v2@132.17,20.791 ; R31.2@132.872,20.521 ccw(c132.438,20.088) 132.438,20.701 ccw(c132.438,21.314) R31.2@132.872,20.881
  Bottom Layer w0.254: v2(85.598,56.007) v2(114.173,56.007) ; v2@85.688,55.917 cw(c85.905,55.7) 85.905,56.007 cw(c85.905,56.314) v2@85.688,56.097 ; v2@114.083,55.917 ccw(c113.866,55.7) 113.866,56.007 ccw(c113.866,56.314) v2@114.083,56.097 ; v2(114.224,36.881) 117.145,36.881 119.151,34.874 119.151,19.914 119.634,19.431 130.81,19.431 v2(132.08,20.701) ; v2@114.314,36.791 cw(c114.53,36.574) 114.53,36.881 cw(c114.53,37.187) v2@114.314,36.971 ; v2@131.953,20.701 cw(c131.646,20.701) 131.863,20.484 cw(c132.08,20.267) v2@132.08,20.574
NetR32_2: R32.2 U10.93 | length 89.7
  Top Layer w0.254: v2@84.619,55.409 cw(c84.402,55.192) 84.709,55.192 cw(c85.016,55.192) v2@84.799,55.409 ; v2(84.709,55.499) 84.709,54.229 86.106,52.832 86.106,45.847 86.273,45.68 U10.93@86.273,43.872 ; v2@113.538,55.245 cw(c113.538,54.938) 113.755,55.155 cw(c113.972,55.372) v2@113.665,55.372 ; v2(113.538,55.372) 115.062,53.848 115.062,38.735 113.817,37.49 v2(113.563,37.49) ; v2@113.563,37.617 ccw(c113.563,38.537) 114.214,37.887 ; v2(120.015,20.574) R32.2@121.895,20.574 ; v2@120.105,20.484 cw(c120.322,20.267) 120.322,20.574 cw(c120.322,20.881) v2@120.105,20.664 ; R32.2@121.696,20.394 ccw(c121.262,19.961) 121.262,20.574 ccw(c121.262,21.187) R32.2@121.696,20.754
  Bottom Layer w0.254: v2(84.709,55.499) 84.734,55.474 85.819,55.474 85.844,55.499 85.958,55.385 113.525,55.385 v2(113.538,55.372) ; v2@84.799,55.589 ccw(c85.077,55.867) 85.077,55.474 ; 113.199,55.385 cw(c113.199,55.033) v2@113.448,55.282 ; 113.264,55.385 ccw(c113.264,55.646) v2@113.448,55.462 ; v2(113.563,37.49) 118.466,37.49 120.015,35.941 v2(120.015,20.574) ; v2@113.653,37.401 cw(c113.87,37.184) 113.87,37.49 cw(c113.87,37.797) v2@113.653,37.58 ; v2@119.925,20.664 ccw(c119.708,20.881) 120.015,20.881 ccw(c120.322,20.881) v2@120.105,20.664
NetR33_2: R33.2 U10.95 | length 66.4
  Top Layer w0.254: v2@83.73,47.789 cw(c83.513,47.572) 83.82,47.572 cw(c84.127,47.572) v2@83.91,47.789 ; v2(83.82,47.879) 83.82,46.609 85.273,45.156 U10.95@85.273,43.872 ; v2@103.339,24.042 ccw(c103.122,24.259) 103.429,24.259 ccw(c103.735,24.259) v2@103.519,24.042 ; v2(103.429,23.952) 103.429,49.581 v2(103.505,49.657) ; 103.429,49.166 cw(c103.996,49.166) v2@103.595,49.567 ; v2@111.111,21.653 cw(c110.527,21.068) R33.2@111.354,21.068 ; R33.2@111.174,20.881 ccw(c110.74,21.314) 111.354,21.314 ccw(c111.967,21.314) R33.2@111.533,20.881 ; v2@111.185,21.616 cw(c111.16,21.424) 111.354,21.424 ; v2@111.201,21.615 111.354,21.463 R33.2@111.354,20.701
  Bottom Layer w0.254: v2(83.82,47.879) 88.9,47.879 90.678,49.657 v2(103.505,49.657) ; v2@83.91,47.789 cw(c84.127,47.572) 84.127,47.879 cw(c84.127,48.186) v2@83.91,47.969 ; v2@103.415,49.567 ccw(c103.198,49.35) 103.198,49.657 ccw(c103.198,49.964) v2@103.415,49.747 ; v2(103.429,23.952) 104.216,24.74 108.204,24.74 v2(111.201,21.742) ; v2@103.429,24.079 ccw(c103.429,24.386) 103.646,24.169 ccw(c103.862,23.952) v2@103.556,23.952 ; v2@111.074,21.742 ccw(c110.768,21.742) 110.984,21.959 ccw(c111.201,22.176) v2@111.201,21.869 ; v2@111.125,21.666 v2@111.201,21.59
NetR37_2: R37.2 U10.5 | length 43
  Top Layer w0.254: v2(49.657,19.812) R37.2@50.673,19.812 ; v2@49.747,19.722 cw(c49.964,19.505) 49.964,19.812 cw(c49.964,20.119) v2@49.747,19.902 ; R37.2@50.474,19.632 ccw(c50.041,19.199) 50.041,19.812 ccw(c50.041,20.425) R37.2@50.474,19.992 ; v2(78.969,40.157) 79.419,40.157 79.584,40.322 U10.5@81.223,40.322 ; v2@79.058,40.068 cw(c79.275,39.851) 79.275,40.157 cw(c79.275,40.464) v2@79.058,40.247
  Bottom Layer w0.254: v2(49.657,19.812) 70.002,40.157 v2(78.969,40.157)
NetR38_2: R38.2 U10.25 | length 29.6
  Top Layer w0.254: R38.2@62.611,19.812 62.611,20.193 63.246,20.828 ; R38.2@62.63,19.812 cw(c63.422,19.88) 62.86,20.442 ; R38.2@62.883,19.834 cw(c64.133,19.941) 63.246,20.828 ; v2@77.292,29.337 cw(c76.986,29.337) 77.202,29.12 cw(c77.419,28.903) v2@77.419,29.21 ; v2(77.419,29.337) 76.327,28.245 76.327,24.003 73.152,20.828 63.246,20.828 ; v2(80.01,29.794) 80.538,30.322 U10.25@81.223,30.322 ; v2@80.01,29.921 ccw(c80.01,30.228) 80.227,30.011 ccw(c80.444,29.794) v2@80.137,29.794 ; 80.388,30.172 ccw(c80.238,30.322) U10.25@80.45,30.322
  Bottom Layer w0.254: v2(77.419,29.337) 77.876,29.794 v2(80.01,29.794) ; v2@77.419,29.464 ccw(c77.419,29.771) 77.636,29.554 ccw(c77.853,29.337) v2@77.546,29.337 ; v2@79.92,29.704 ccw(c79.703,29.488) 79.703,29.794 ccw(c79.703,30.101) v2@79.92,29.884
NetR39_2: R39.2 U10.26 | length 17.9
  Top Layer w0.254: R39.2@74.242,19.992 ccw(c73.809,20.425) 74.422,20.425 ccw(c75.035,20.425) R39.2@74.602,19.992 ; R39.2@74.422,19.812 74.422,20.828 76.962,23.368 76.962,27.305 v2(77.368,27.711) ; v2@77.241,27.711 cw(c76.935,27.711) 77.152,27.495 cw(c77.368,27.278) v2@77.368,27.584 ; v2(80.34,28.397) 81.61,28.397 81.985,28.772 U10.26@82.773,28.772 ; v2@80.43,28.307 cw(c80.647,28.091) 80.647,28.397 cw(c80.647,28.704) v2@80.43,28.487
  Bottom Layer w0.254: v2(77.368,27.711) 78.054,28.397 v2(80.34,28.397) ; v2@77.368,27.838 ccw(c77.368,28.145) 77.585,27.928 ccw(c77.802,27.711) v2@77.495,27.711 ; v2@80.25,28.307 ccw(c80.034,28.091) 80.034,28.397 ccw(c80.034,28.704) v2@80.25,28.487
NetR40_2: R40.2 U10.40 | length 14.7
  Top Layer w0.254: R40.2@86.614,19.812 86.614,20.117 87.909,21.412 87.909,24.679 v2(88.199,24.968) ; R40.2@86.633,19.812 cw(c87.415,19.812) 86.862,20.365 ; R40.2@86.887,19.812 cw(c88.282,19.812) 87.296,20.798 ; v2@88.072,24.968 cw(c87.765,24.968) 87.982,24.751 cw(c88.199,24.535) v2@88.199,24.841 ; v2@89.445,26.709 ccw(c88.654,27.5) 89.773,27.5 ; v2(89.535,26.619) 89.773,26.857 U10.40@89.773,28.772 ; v2@89.625,26.529 ccw(c89.267,26.887) 89.773,26.887
  Bottom Layer w0.254: v2@88.109,25.058 ccw(c87.892,25.275) 88.199,25.275 ccw(c88.506,25.275) v2@88.289,25.058 ; v2(88.199,24.968) 88.199,25.283 v2(89.535,26.619) ; v2@89.408,26.619 cw(c89.101,26.619) 89.318,26.402 cw(c89.535,26.186) v2@89.535,26.492
NetR41_2: R41.2 U10.42 | length 19.9
  Top Layer w0.254: v2@90.207,20.156 ccw(c89.99,20.373) 90.297,20.373 ccw(c90.604,20.373) v2@90.387,20.156 ; v2(90.297,20.066) 90.297,25.451 90.773,25.927 U10.42@90.773,28.772 ; v2(97.536,19.812) R41.2@98.806,19.812 ; v2@97.626,19.722 cw(c97.843,19.505) 97.843,19.812 cw(c97.843,20.119) v2@97.626,19.902 ; R41.2@98.607,19.632 ccw(c98.174,19.199) 98.174,19.812 ccw(c98.174,20.425) R41.2@98.607,19.992
  Bottom Layer w0.254: v2(90.297,20.066) 97.282,20.066 v2(97.536,19.812) ; v2@90.387,19.976 cw(c90.604,19.759) 90.604,20.066 cw(c90.604,20.373) v2@90.387,20.156
NetR47_1: R47.1 U3.14 | length 5.2
  Top Layer w0.254: U3.14@119.091,44.831 122.555,44.831 R47.1@122.682,44.958 ; U3.14@119.775,44.705 cw(c120.079,44.402) 120.079,44.831 cw(c120.079,45.26) U3.14@119.775,44.957 ; 122.018,44.831 ccw(c122.018,45.547) R47.1@122.524,45.041 ; 122.269,44.831 cw(c122.269,44.47) R47.1@122.524,44.725
NetR57_1: R57.1 U10.70 | length 43.6
  Top Layer w0.254: U10.70@96.323,39.822 97.988,39.822 98.958,40.792 98.958,47.752 98.908,47.803 98.908,52.172 v2(99.441,52.705) ; v2@99.314,52.705 cw(c99.007,52.705) 99.224,52.488 cw(c99.441,52.271) v2@99.441,52.578 ; v2@109.511,52.795 ccw(c109.294,53.012) 109.601,53.012 ccw(c109.908,53.012) v2@109.691,52.795 ; v2(109.601,52.705) 109.601,54.102 109.982,54.483 R57.1@109.982,67.945 ; R57.1@109.802,67.765 cw(c109.369,67.332) 109.982,67.332 cw(c110.595,67.332) R57.1@110.162,67.765
  Bottom Layer w0.254: v2(99.441,52.705) v2(109.601,52.705) ; v2@99.531,52.615 cw(c99.748,52.398) 99.748,52.705 cw(c99.748,53.012) v2@99.531,52.795 ; v2@109.511,52.615 ccw(c109.294,52.398) 109.294,52.705 ccw(c109.294,53.012) v2@109.511,52.795
NetR60_1: R60.1 U3.13 | length 5.3
  Top Layer w0.254: U3.13@119.091,43.561 120.904,43.561 121.454,43.011 R60.1@122.682,43.011 ; U3.13@119.775,43.435 cw(c120.079,43.132) 120.079,43.561 cw(c120.079,43.99) U3.13@119.775,43.687 ; R60.1@122.524,42.853 ccw(c122.144,42.472) 122.144,43.011 ccw(c122.144,43.549) R60.1@122.524,43.168
NetR61_1: R61.1 R69.1 U8.6 | length 8.2
  Top Layer w0.254: U8.6@118.653,24.765 120.015,24.765 120.495,24.285 R69.1@121.793,24.285 R61.1@121.793,22.733 ; U8.6@119.169,24.63 cw(c119.494,24.305) 119.494,24.765 cw(c119.494,25.225) U8.6@119.169,24.9 ; R61.1@121.635,22.966 ccw(c121.255,23.346) 121.793,23.346 ccw(c122.331,23.346) R61.1@121.951,22.966 ; R69.1@121.635,24.053 cw(c121.255,23.672) 121.793,23.672 cw(c122.331,23.672) R69.1@121.951,24.053 ; R69.1@121.635,24.128 ccw(c121.255,23.747) 121.255,24.285 ccw(c121.255,24.824) R69.1@121.635,24.443
NetR62_1: R62.1 R70.1 U8.7 | length 8
  Top Layer w0.254: U8.7@118.653,26.035 120.015,26.035 120.213,25.837 R62.1@121.793,25.837 R70.1@121.793,27.39 ; U8.7@119.169,25.9 cw(c119.494,25.575) 119.494,26.035 cw(c119.494,26.495) U8.7@119.169,26.17 ; R62.1@121.635,25.68 ccw(c121.255,25.299) 121.255,25.837 ccw(c121.255,26.376) R62.1@121.635,25.995 ; R62.1@121.635,26.07 ccw(c121.255,26.451) 121.793,26.451 ccw(c122.331,26.451) R62.1@121.951,26.07 ; R70.1@121.635,27.157 cw(c121.255,26.776) 121.793,26.776 cw(c122.331,26.776) R70.1@121.951,27.157
NetR64_2: R64.2 U5.3 | length 2
  Bottom Layer w0.254: U5.3@34.554,70.644 34.535,70.663 36.404,70.663 R64.2@36.462,70.605
NetR65_2: R65.2 U6.3 | length 2.7
  Bottom Layer w0.508: U6.3@59.002,85.7 60.681,85.7 60.954,85.427 R65.2@60.954,84.772
NetR73_1: R73.1 R75.1 U9.6 | length 8
  Top Layer w0.254: U9.6@118.653,32.089 121.75,32.089 R75.1@121.793,32.046 R73.1@121.793,30.494 ; U9.6@119.169,31.954 cw(c119.494,31.629) 119.494,32.089 cw(c119.494,32.549) U9.6@119.169,32.224 ; 121.176,32.089 ccw(c121.176,32.738) R75.1@121.635,32.279 ; 121.333,32.089 cw(c121.333,31.661) R75.1@121.635,31.964 ; R73.1@121.635,30.727 ccw(c121.255,31.107) 121.793,31.107 ccw(c122.331,31.107) R73.1@121.951,30.727 ; R75.1@121.635,31.814 cw(c121.255,31.433) 121.793,31.433 cw(c122.331,31.433) R75.1@121.951,31.814
NetR74_1: R74.1 R76.1 U9.7 | length 8.5
  Top Layer w0.254: U9.7@118.653,33.359 121.553,33.359 R74.1@121.793,33.599 R76.1@121.793,35.151 ; U9.7@119.169,33.224 cw(c119.494,32.899) 119.494,33.359 cw(c119.494,33.819) U9.7@119.169,33.494 ; 120.857,33.359 ccw(c120.857,34.459) R74.1@121.635,33.681 ; R74.1@121.47,33.359 ccw(c121.47,33.846) R74.1@121.815,33.502 ; R74.1@121.635,33.831 ccw(c121.255,34.212) 121.793,34.212 ccw(c122.331,34.212) R74.1@121.951,33.831 ; R76.1@121.635,34.918 cw(c121.255,34.537) 121.793,34.537 cw(c122.331,34.537) R76.1@121.951,34.918
NetR79_2: R79.2 U10.94 | length 5.6
  Top Layer w0.254: R79.2@84.783,47.934 cw(c84.35,47.501) 84.963,47.501 cw(c85.576,47.501) R79.2@85.143,47.934 ; R79.2@84.963,48.133 84.963,46.228 85.773,45.418 U10.94@85.773,43.872
NetR87_2: R87.2 U7.3 | length 2
  Bottom Layer w0.508: U7.3@45.654,70.644 47.561,70.644 R87.2@47.6,70.605
NetR88_2: R88.2 U12.3 | length 2.3
  Bottom Layer w0.508: U12.3@47.127,85.7 48.081,85.7 R88.2@49.009,84.772
NetR99_2: R99.2 U13.3 | length 2
  Bottom Layer w0.254: U13.3@56.754,70.644 58.699,70.644 R99.2@58.737,70.605
NetR100_2: R100.2 U14.3 | length 2.6
  Bottom Layer w0.254: U14.3@35.253,85.7 36.805,85.7 37.084,85.42 37.084,84.791 R100.2@37.065,84.772
NetR111_2: R111.2 U15.3 | length 2
  Bottom Layer w0.508: U15.3@67.854,70.644 69.836,70.644 R111.2@69.875,70.605
NetR112_2: R112.2 U16.3 | length 2.6
  Bottom Layer w0.254: U16.3@23.378,85.7 23.505,85.827 24.663,85.827 25.121,85.369 R112.2@25.121,84.772
NetU10_1: U10.1
NetU10_2: U10.2
NetU10_38: U10.38
NetU10_39: U10.39
NetU10_41: U10.41
NetU10_43: U10.43
NetU10_45: U10.45
NetU10_46: U10.46
NetU10_51: U10.51
NetU10_52: U10.52
NetU10_53: U10.53
NetU10_54: U10.54
NetU10_58: U10.58
NetU10_59: U10.59
NetU10_61: U10.61
NetU10_62: U10.62
NetU10_65: U10.65
NetU10_66: U10.66
NetU10_71: U10.71
NetU10_78: U10.78
NetU10_79: U10.79
NetU10_80: U10.80
NetU10_81: U10.81
NetU10_82: U10.82
NetU10_83: U10.83
NetU10_85: U10.85
NetU10_86: U10.86
NetU10_87: U10.87
NetU10_88: U10.88
NetU10_89: U10.89
NetU10_90: U10.90
NetU10_91: U10.91
RXD1_485: U8.1 U10.64 | length 25.7
  Top Layer w0.254: U10.64@96.323,36.822 96.34,36.805 99.339,36.805 100.838,35.306 100.813,35.281 v2(100.813,30.937) ; v2@100.723,31.027 ccw(c100.506,31.244) 100.813,31.244 ccw(c101.119,31.244) v2@100.902,31.027 ; v2(106.375,30.886) 107.671,30.886 111.252,27.305 U8.1@112.903,27.305 ; v2@106.465,30.797 cw(c106.682,30.58) 106.682,30.886 cw(c106.682,31.193) v2@106.465,30.976 ; U8.1@112.387,27.17 ccw(c112.062,26.845) 112.062,27.305 ccw(c112.062,27.765) U8.1@112.387,27.44
  Bottom Layer w0.254: v2(100.813,30.937) 106.324,30.937 v2(106.375,30.886) ; v2@100.902,30.847 cw(c101.119,30.631) 101.119,30.937 cw(c101.119,31.244) v2@100.902,31.027 ; 105.946,30.937 cw(c105.946,30.457) v2@106.285,30.797
RXD2_485: R12.2 U9.1 U10.48 | length 116.3
  Top Layer w0.254: R12.2@91.768,88.955 cw(c91.335,88.522) 91.948,88.522 cw(c92.561,88.522) R12.2@92.128,88.955 ; v2@91.858,87.466 ccw(c91.641,87.683) 91.948,87.683 ccw(c92.255,87.683) v2@92.038,87.466 ; v2(91.948,87.376) R12.2@91.948,89.154 ; v2(92.964,69.215) v2(105.41,69.215) ; v2@93.054,69.125 cw(c93.271,68.908) 93.271,69.215 cw(c93.271,69.522) v2@93.054,69.305 ; v2(93.218,26.416) 93.662,26.86 93.662,26.868 93.806,27.012 93.806,28.739 U10.48@93.773,28.772 ; v2@93.218,26.543 ccw(c93.218,26.85) 93.435,26.633 ccw(c93.652,26.416) v2@93.345,26.416 ; v2@105.32,69.125 ccw(c105.103,68.908) 105.103,69.215 ccw(c105.103,69.522) v2@105.32,69.305 ; v2@105.447,60.743 cw(c105.23,60.526) 105.537,60.526 cw(c105.844,60.526) v2@105.627,60.743 ; v2(105.537,60.833) 105.537,58.293 106.553,57.277 v2(106.553,34.629) ; v2@106.463,34.719 ccw(c106.246,34.936) 106.553,34.936 ccw(c106.86,34.936) v2@106.643,34.719 ; v2(111.21,34.629) U9.1@112.903,34.629 114.342,34.629 115.189,33.782 115.189,31.369 v2(114.681,30.861) ; v2@111.3,34.539 cw(c111.517,34.322) 111.517,34.629 cw(c111.517,34.936) v2@111.3,34.719 ; U9.1@112.387,34.494 ccw(c112.062,34.169) 112.062,34.629 ccw(c112.062,35.089) U9.1@112.387,34.764 ; U9.1@113.419,34.494 cw(c113.744,34.169) 113.744,34.629 cw(c113.744,35.089) U9.1@113.419,34.764 ; v2@114.681,30.988 ccw(c114.681,31.295) 114.898,31.078 ccw(c115.115,30.861) v2@114.808,30.861
  Bottom Layer w0.254: v2@91.948,87.249 cw(c91.948,86.942) 92.165,87.159 cw(c92.382,87.376) v2@92.075,87.376 ; v2(91.948,87.376) 92.964,86.36 v2(92.964,69.215) ; v2@92.874,69.305 ccw(c92.657,69.522) 92.964,69.522 ccw(c93.271,69.522) v2@93.054,69.305 ; v2(93.218,26.416) 93.345,26.289 98.45,26.289 101.346,29.185 110.16,29.185 111.303,30.328 ; v2@93.308,26.506 ccw(c93.831,27.029) 93.831,26.289 ; v2@105.32,69.125 cw(c104.797,68.602) 105.537,68.602 ; v2(105.41,69.215) 105.537,69.088 v2(105.537,60.833) ; v2@105.447,60.923 ccw(c105.23,61.14) 105.537,61.14 ccw(c105.844,61.14) v2@105.627,60.923 ; v2(106.553,34.629) v2(111.21,34.629) ; v2@106.643,34.539 cw(c106.86,34.322) 106.86,34.629 cw(c106.86,34.936) v2@106.643,34.719 ; v2@111.12,34.539 ccw(c110.903,34.322) 110.903,34.629 ccw(c110.903,34.936) v2@111.12,34.719 ; 111.328,30.302 111.887,30.861 v2(114.681,30.861) ; v2@114.591,30.771 ccw(c114.374,30.554) 114.374,30.861 ccw(c114.374,31.168) v2@114.591,30.951
RXD_233: U3.12 U10.24 | length 48.5
  Top Layer w0.254: U10.24@81.223,30.822 82.511,30.822 86.233,34.544 v2(86.233,36.322) ; v2@86.143,36.232 cw(c85.926,36.015) 86.233,36.015 cw(c86.54,36.015) v2@86.323,36.232 ; v2(111.125,36.322) 114.808,36.322 116.459,37.973 116.459,41.529 117.221,42.291 U3.12@119.091,42.291 ; v2@111.215,36.232 cw(c111.432,36.015) 111.432,36.322 cw(c111.432,36.629) v2@111.215,36.412 ; U3.12@118.406,42.165 ccw(c118.103,41.862) 118.103,42.291 ccw(c118.103,42.72) U3.12@118.406,42.417
  Bottom Layer w0.254: v2(86.233,36.322) v2(111.125,36.322) v2@111.252,36.322 ; v2@86.323,36.232 cw(c86.54,36.015) 86.54,36.322 cw(c86.54,36.629) v2@86.323,36.412 ; v2@111.035,36.232 ccw(c110.818,36.015) 110.818,36.322 ccw(c110.818,36.629) v2@111.035,36.412
SWCLK: SWD1.3 U10.76 | length 11.1
  Top Layer w0.254: SWD1.3@93.345,54.356 93.345,52.324 94.773,50.896 U10.76@94.773,43.872
SWDIO: SWD1.2 U10.72 | length 15.9
  Top Layer w0.254: SWD1.2@95.885,54.356 95.885,51.57 97.409,50.046 97.409,45.568 98.146,44.831 98.146,41.504 97.464,40.822 U10.72@96.323,40.822
TXD1_485: U8.4 U10.63 | length 32
  Top Layer w0.254: U10.63@96.323,36.322 98.933,36.322 100.279,34.976 v2(100.279,26.086) ; v2@100.189,26.176 ccw(c99.973,26.392) 100.279,26.392 ccw(c100.586,26.392) v2@100.369,26.176 ; v2@110.908,25.234 cw(c110.691,25.017) 110.998,25.017 cw(c111.305,25.017) v2@111.088,25.234 ; v2@110.998,25.349 v2(110.998,25.324) 110.998,24.384 111.887,23.495 U8.4@112.903,23.495 ; U8.4@112.387,23.36 ccw(c112.062,23.035) 112.062,23.495 ccw(c112.062,23.955) U8.4@112.387,23.63
  Bottom Layer w0.254: v2(100.279,26.086) 102.26,28.067 108.255,28.067 v2(110.998,25.324) v2@111.049,25.273 ; v2@100.279,26.213 ccw(c100.279,26.519) 100.496,26.303 ccw(c100.713,26.086) v2@100.406,26.086 ; v2@110.871,25.324 ccw(c110.564,25.324) 110.781,25.541 ccw(c110.998,25.757) v2@110.998,25.451
TXD2_485: R10.2 U9.4 U10.47 | length 109.9
  Top Layer w0.254: R10.2@87.323,88.955 cw(c86.89,88.522) 87.503,88.522 cw(c88.116,88.522) R10.2@87.683,88.955 ; v2@87.413,87.593 ccw(c87.196,87.81) 87.503,87.81 ccw(c87.81,87.81) v2@87.593,87.593 ; v2(87.503,67.437) v2(106.426,67.437) ; v2(87.503,87.503) R10.2@87.503,89.154 ; v2@87.593,67.347 cw(c87.81,67.13) 87.81,67.437 cw(c87.81,67.744) v2@87.593,67.527 ; v2@93.183,27.323 ccw(c92.966,27.54) 93.273,27.54 ccw(c93.58,27.54) v2@93.363,27.323 ; v2(93.273,27.233) U10.47@93.273,28.772 ; v2@106.336,67.347 ccw(c106.119,67.13) 106.119,67.437 ccw(c106.119,67.744) v2@106.336,67.527 ; v2@106.463,60.743 cw(c106.246,60.526) 106.553,60.526 cw(c106.86,60.526) v2@106.643,60.743 ; v2(106.553,60.833) 106.553,58.293 107.188,57.658 107.188,32.131 108.5,30.819 v2(109.982,30.819) U9.4@112.903,30.819 ; v2@109.892,30.729 ccw(c109.675,30.512) 109.675,30.819 ccw(c109.675,31.126) v2@109.892,30.909 ; v2@110.072,30.729 cw(c110.289,30.512) 110.289,30.819 cw(c110.289,31.126) v2@110.072,30.909 ; U9.4@112.387,30.684 ccw(c112.062,30.359) 112.062,30.819 ccw(c112.062,31.279) U9.4@112.387,30.954
  Bottom Layer w0.254: v2@87.413,67.527 ccw(c87.196,67.744) 87.503,67.744 ccw(c87.81,67.744) v2@87.593,67.527 ; v2@87.413,87.413 cw(c87.196,87.196) 87.503,87.196 cw(c87.81,87.196) v2@87.593,87.413 ; v2(87.503,67.437) v2(87.503,87.503) ; v2(93.273,27.233) 98.404,27.233 101.016,29.845 109.017,29.845 v2@110.007,30.836 ; v2@93.363,27.143 cw(c93.58,26.926) 93.58,27.233 cw(c93.58,27.54) v2@93.363,27.323 ; v2@106.336,67.347 cw(c105.813,66.824) 106.553,66.824 ; v2(106.426,67.437) 106.553,67.31 v2(106.553,60.833) ; v2@106.463,60.923 ccw(c106.246,61.14) 106.553,61.14 ccw(c106.86,61.14) v2@106.643,60.923
TXD_232: R15.2 U3.11 U10.23 | length 53
  Top Layer w0.254: U10.23@81.223,31.322 82.376,31.322 85.471,34.417 v2(85.471,35.814) ; v2@85.381,35.724 cw(c85.164,35.507) 85.471,35.507 cw(c85.778,35.507) v2@85.561,35.724 ; v2(111.125,35.56) 115.062,35.56 117.094,37.592 117.094,40.64 117.475,41.021 U3.11@119.091,41.021 R15.2@122.682,41.021 ; v2@111.215,35.47 cw(c111.432,35.253) 111.432,35.56 cw(c111.432,35.867) v2@111.215,35.65 ; U3.11@118.406,40.895 ccw(c118.103,40.592) 118.103,41.021 ccw(c118.103,41.45) U3.11@118.406,41.147 ; U3.11@119.775,40.895 cw(c120.079,40.592) 120.079,41.021 cw(c120.079,41.45) U3.11@119.775,41.147 ; R15.2@122.524,40.863 ccw(c122.144,40.483) 122.144,41.021 ccw(c122.144,41.559) R15.2@122.524,41.179
  Bottom Layer w0.254: v2(85.471,35.814) 85.496,35.789 110.896,35.789 v2(111.125,35.56) ; v2@85.561,35.904 ccw(c85.839,36.182) 85.839,35.789 ; 110.267,35.789 cw(c110.267,34.702) v2@111.035,35.47 ; 110.88,35.789 cw(c110.88,35.315) v2@111.215,35.65
V5.0: C2.1 C4.2 C13.2 C14.2 C15.2 C16.2 C17.2 C47.2 L1.2 P5.1 P17.3 R50.1 R56.2 U1.4 U11.8 VR1.3 | length 322
  Top Layer w0.508: 16.002,31.267 17.297,31.267 18.923,32.893 25.047,32.893 VR1.3@26.035,31.905 ; v1(16.561,18.364) 17.958,18.364 20.193,16.129 v2(20.193,14.097) 21.873,14.097 21.914,14.056 ; 25.274,32.666 cw(c24.512,31.905) VR1.3@25.589,31.905 ; v3(85.598,85.598) 95.377,85.598 96.901,84.074 C47.2@96.901,80.645 96.815,80.731 93.415,80.731 ; v3@85.778,85.418 cw(c86.211,84.985) 86.211,85.598 cw(c86.211,86.211) v3@85.778,85.778 ; 96.433,80.731 cw(c96.433,80.196) C47.2@96.811,80.574
  Top Layer w0.762: C15.2@4.445,11.43 C14.2@4.445,12.954 4.445,17.653 6.858,20.066 v1(14.072,20.066) 14.58,20.066 16.002,21.488 16.002,30.099 ; C17.2@12.56,31.242 14.859,31.242 16.002,30.099 ; v1(13.716,46.99) 13.716,39.675 13.716,36.83 16.002,34.544 16.002,31.267 16.002,30.099 ; v1(32.004,14.351) R50.1@32.004,13.335 32.16,13.335 37.748,7.747 45.343,7.747 46.076,7.015 P17.3@46.076,3.991 ; v3(45.515,37.924) U1.4@48.514,37.924 ; v1(56.388,54.483) 81.153,54.483 v1(85.725,59.055) ; v1(85.725,70.358) 101.981,70.358 103.505,71.882 R56.2@104.394,71.882
  Top Layer w1.27: 13.716,39.675 13.837,39.554 C4.2@16.129,39.554 21.279,39.554 C2.1@21.336,39.497 C2.1@21.59,39.751 ; v3(21.971,44.831) C13.2@21.971,42.926 21.971,40.132 C2.1@21.59,39.751 ; VR1.3@26.035,31.905 26.035,34.671 24.511,36.195 24.511,39.751 ; L1.2@27.281,39.139 ccw(c25.805,37.663) 25.805,39.751 ccw(c25.805,41.839) L1.2@27.281,40.363 ; L1.2@27.893,39.751 24.511,39.751 ; C2.1@21.59,39.751 24.511,39.751
  Bottom Layer w0.508: v1(14.072,20.066) 15.773,18.364 v1(16.561,18.364) ; v2(20.193,14.097) 23.901,14.097 24.968,13.03 30.683,13.03 v1(32.004,14.351) ; v3(45.515,37.924) v3@45.564,37.973 ; P5.1@85.511,96.641 85.598,96.553 v3(85.598,85.598) ; v1(85.725,70.358) 85.725,85.725 v3@85.778,85.778
  Bottom Layer w0.762: v1(13.716,46.99) 14.922,48.197 50.102,48.197 v1(56.388,54.483) ; v3(21.971,44.831) 38.608,44.831 v3(45.515,37.924) ; v1(85.725,59.055) v1(85.725,70.358)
